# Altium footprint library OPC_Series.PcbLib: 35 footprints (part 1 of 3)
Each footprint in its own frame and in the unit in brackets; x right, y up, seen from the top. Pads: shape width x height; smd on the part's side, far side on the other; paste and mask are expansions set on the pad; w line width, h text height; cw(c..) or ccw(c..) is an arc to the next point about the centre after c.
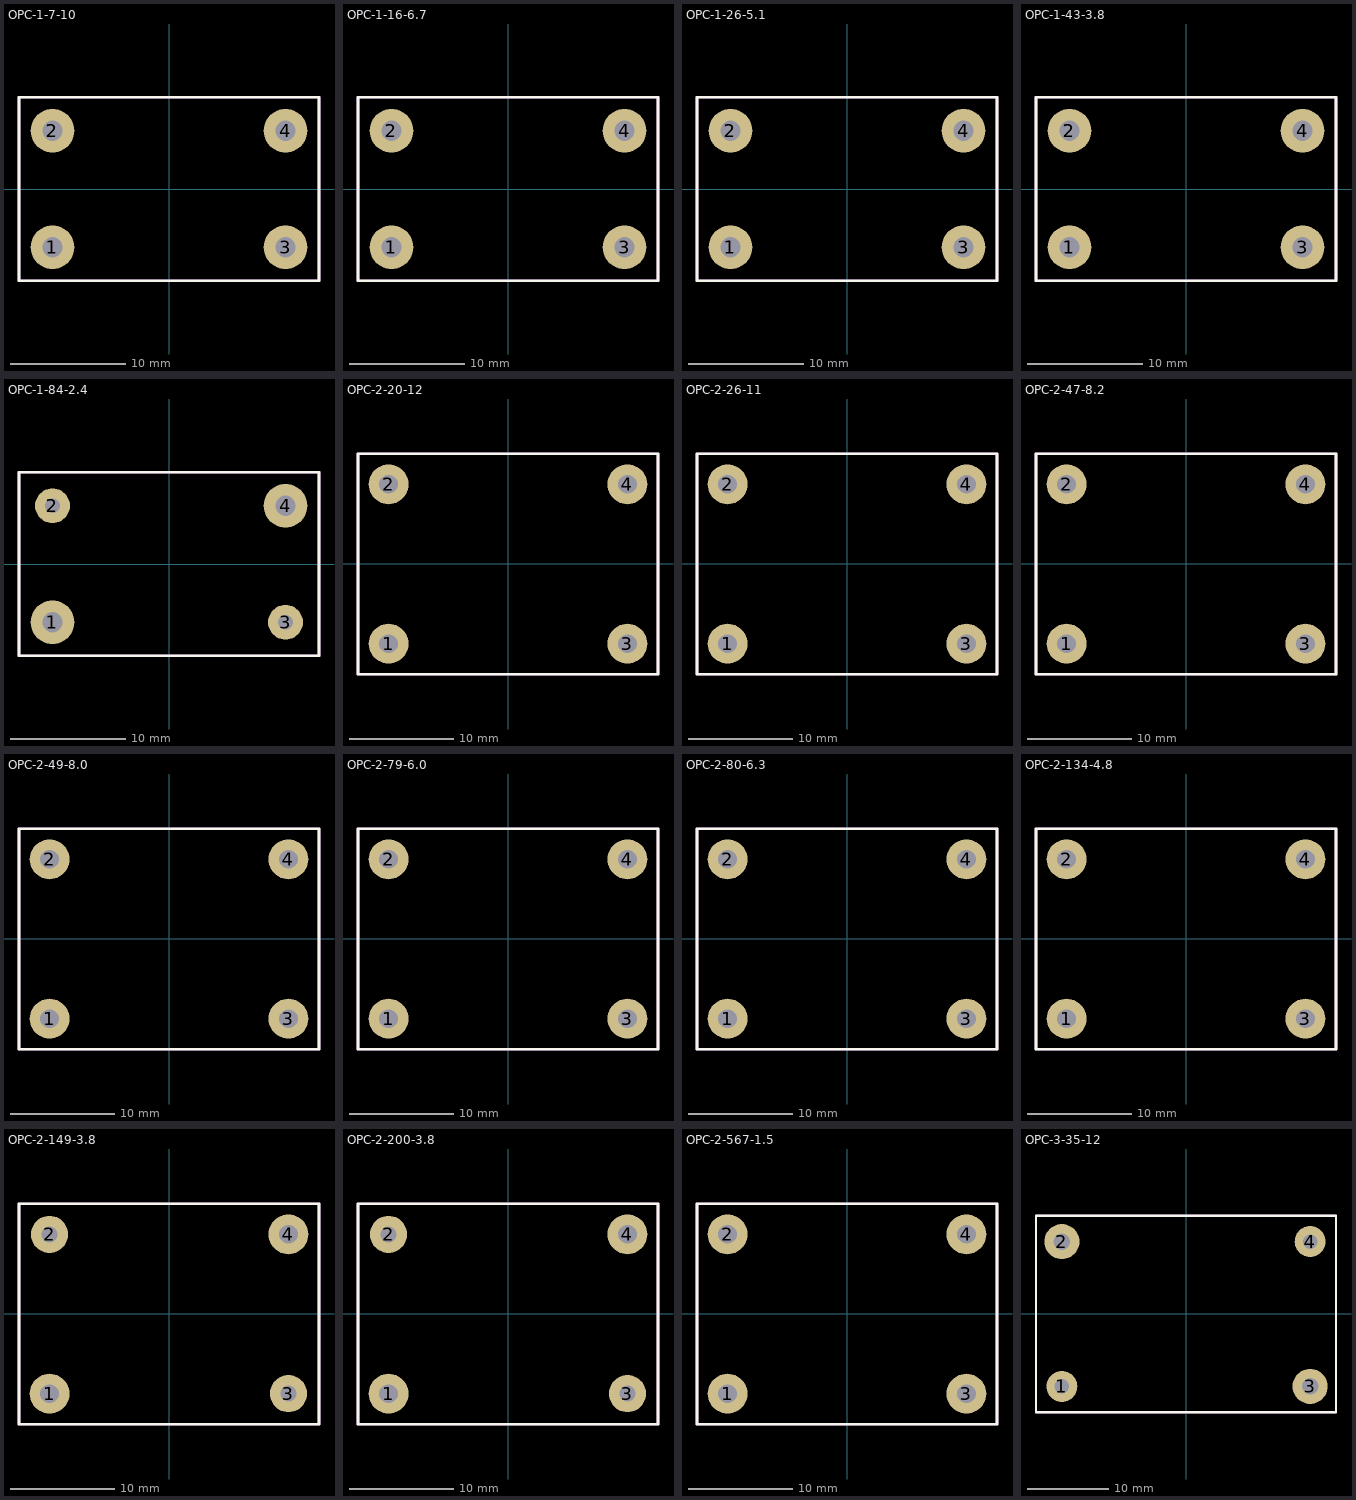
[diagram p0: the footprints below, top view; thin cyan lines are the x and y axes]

## OPC-1-7-10 [mil]
pads (4):
  round 150 hole 70: 1(-400,-200) 2(-400,200) 3(400,-200) 4(400,200)
Top Overlay:
  lines w10: 515,-120 515,315 -515,315 -515,-315 515,-315 515,-110
Mechanical 29:
  lines w10: 515,-120 515,315 -515,315 -515,-315 515,-315 515,-110
  text "'.Designator'" at -1750,-64.85 h400

## OPC-1-16-6.7 [mil]
pads (4):
  round 150 hole 70: 1(-400,-200) 2(-400,200) 3(400,-200) 4(400,200)
Top Overlay:
  lines w10: 515,-120 515,315 -515,315 -515,-315 515,-315 515,-110
Mechanical 29:
  lines w10: 515,-120 515,315 -515,315 -515,-315 515,-315 515,-110
  text "'.Designator'" at -1750,-64.85 h400

## OPC-1-26-5.1 [mil]
pads (4):
  round 150 hole 70: 1(-400,-200) 2(-400,200) 3(400,-200) 4(400,200)
Top Overlay:
  lines w10: 515,-120 515,315 -515,315 -515,-315 515,-315 515,-110
Mechanical 29:
  lines w10: 515,-120 515,315 -515,315 -515,-315 515,-315 515,-110
  text "'.Designator'" at -1750,-64.85 h400

## OPC-1-43-3.8 [mil]
pads (4):
  round 150 hole 70: 1(-400,-200) 2(-400,200) 3(400,-200) 4(400,200)
Top Overlay:
  lines w10: 515,-120 515,315 -515,315 -515,-315 515,-315 515,-110
Mechanical 29:
  lines w10: 515,-120 515,315 -515,315 -515,-315 515,-315 515,-110
  text "'.Designator'" at -1750,-64.85 h400

## OPC-1-84-2.4 [mil]
pads (4):
  round 150 hole 70: 1(-400,-200) 4(400,200)
  round 120 hole 50: 2(-400,200) 3(400,-200)
Top Overlay:
  lines w10: 515,-120 515,315 -515,315 -515,-315 515,-315 515,-110
Mechanical 29:
  lines w10: 515,-120 515,315 -515,315 -515,-315 515,-315 515,-110
  text "'.Designator'" at -1750,-64.85 h400

## OPC-2-20-12 [mil]
pads (4):
  round 150 hole 70: 1(-450,-300) 2(-450,300) 3(450,-300) 4(450,300)
Top Overlay:
  lines w10: 565,-120 565,415 -565,415 -565,-415 565,-415 565,-110
Mechanical 29:
  lines w10: 565,-120 565,415 -565,415 -565,-415 565,-415 565,-110
  text "'.Designator'" at -1750,-64.85 h400

## OPC-2-26-11 [mil]
pads (4):
  round 150 hole 70: 1(-450,-300) 2(-450,300) 3(450,-300) 4(450,300)
Top Overlay:
  lines w10: 565,-120 565,415 -565,415 -565,-415 565,-415 565,-110
Mechanical 29:
  lines w10: 565,-120 565,415 -565,415 -565,-415 565,-415 565,-110
  text "'.Designator'" at -1750,-64.85 h400

## OPC-2-47-8.2 [mil]
pads (4):
  round 150 hole 70: 1(-450,-300) 2(-450,300) 3(450,-300) 4(450,300)
Top Overlay:
  lines w10: 565,-120 565,415 -565,415 -565,-415 565,-415 565,-110
Mechanical 29:
  lines w10: 565,-120 565,415 -565,415 -565,-415 565,-415 565,-110
  text "'.Designator'" at -1750,-64.85 h400

## OPC-2-49-8.0 [mil]
pads (4):
  round 150 hole 70: 1(-450,-300) 2(-450,300) 3(450,-300) 4(450,300)
Top Overlay:
  lines w10: 565,-120 565,415 -565,415 -565,-415 565,-415 565,-110
Mechanical 29:
  lines w10: 565,-120 565,415 -565,415 -565,-415 565,-415 565,-110
  text "'.Designator'" at -1750,-64.85 h400

## OPC-2-79-6.0 [mil]
pads (4):
  round 150 hole 70: 1(-450,-300) 2(-450,300) 3(450,-300) 4(450,300)
Top Overlay:
  lines w10: 565,-120 565,415 -565,415 -565,-415 565,-415 565,-110
Mechanical 29:
  lines w10: 565,-120 565,415 -565,415 -565,-415 565,-415 565,-110
  text "'.Designator'" at -1750,-64.85 h400

## OPC-2-80-6.3 [mil]
pads (4):
  round 150 hole 70: 1(-450,-300) 2(-450,300) 3(450,-300) 4(450,300)
Top Overlay:
  lines w10: 565,-120 565,415 -565,415 -565,-415 565,-415 565,-110
Mechanical 29:
  lines w10: 565,-120 565,415 -565,415 -565,-415 565,-415 565,-110
  text "'.Designator'" at -1750,-64.85 h400

## OPC-2-134-4.8 [mil]
pads (4):
  round 150 hole 70: 1(-450,-300) 2(-450,300) 3(450,-300) 4(450,300)
Top Overlay:
  lines w10: 565,-120 565,415 -565,415 -565,-415 565,-415 565,-110
Mechanical 29:
  lines w10: 565,-120 565,415 -565,415 -565,-415 565,-415 565,-110
  text "'.Designator'" at -1750,-64.85 h400

## OPC-2-149-3.8 [mil]
pads (4):
  round 150 hole 70: 1(-450,-300) 4(450,300)
  round 140 hole 60: 2(-450,300) 3(450,-300)
Top Overlay:
  lines w10: 565,-120 565,415 -565,415 -565,-415 565,-415 565,-110
Mechanical 29:
  lines w10: 565,-120 565,415 -565,415 -565,-415 565,-415 565,-110
  text "'.Designator'" at -1750,-64.85 h400

## OPC-2-200-3.8 [mil]
pads (4):
  round 150 hole 70: 1(-450,-300) 4(450,300)
  round 140 hole 60: 2(-450,300) 3(450,-300)
Top Overlay:
  lines w10: 565,-120 565,415 -565,415 -565,-415 565,-415 565,-110
Mechanical 29:
  lines w10: 565,-120 565,415 -565,415 -565,-415 565,-415 565,-110
  text "'.Designator'" at -1750,-64.85 h400

## OPC-2-567-1.5 [mil]
pads (4):
  round 150 hole 70: 1(-450,-300) 2(-450,300) 3(450,-300) 4(450,300)
Top Overlay:
  lines w10: 565,-120 565,415 -565,415 -565,-415 565,-415 565,-110
Mechanical 29:
  lines w10: 565,-120 565,415 -565,415 -565,-415 565,-415 565,-110
  text "'.Designator'" at -1750,-64.85 h400

## OPC-3-35-12 [mil]
pads (4):
  round 150 hole 70: 1(-600,-350) 4(600,350)
  round 170 hole 80: 2(-600,350) 3(600,-350)
Top Overlay:
  lines w10: -725,-475 -725,-110 -725,475 725,475 725,110 725,-475 -725,-475
Mechanical 29:
  lines w10: -725,-475 -725,-110 -725,475 725,475 725,110 725,-475 -725,-475
  text "'.Designator'" at -1750,-64.85 h400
